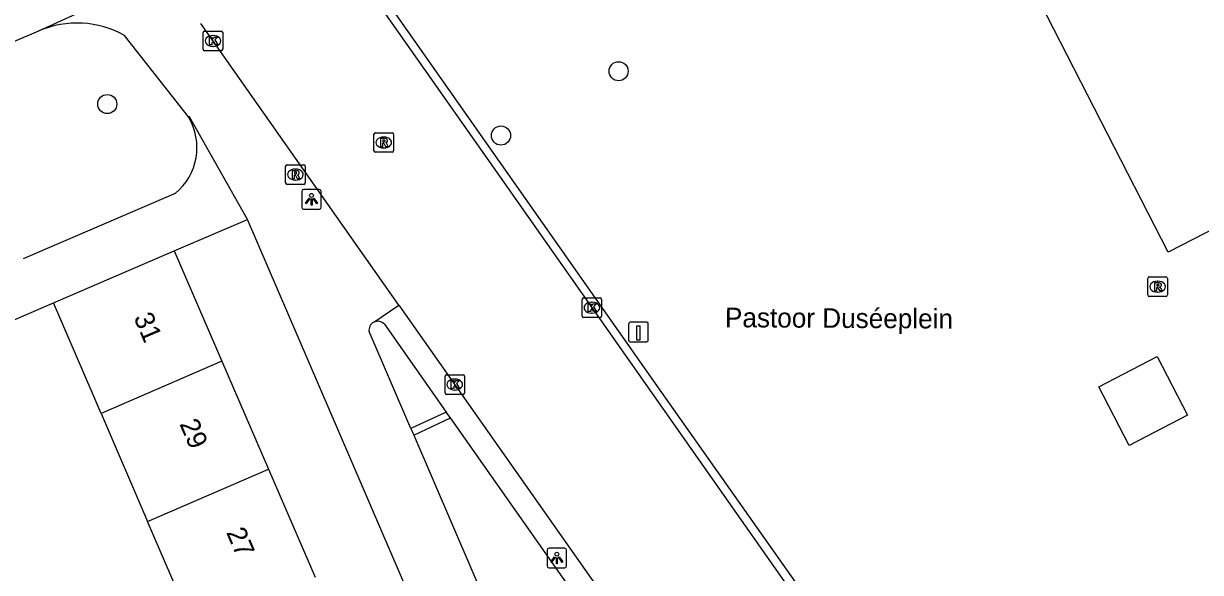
# Model space of a CAD drawing. Extents: x 159353 to 160616, y 385893 to 387321.
# Drawn here: x 159691.6 to 159751.8, y 386412.6 to 386440.7 of the extents above; entities that cross this region are included whole.
import ezdxf

# ---------------------------------------------------------------- set-up
doc = ezdxf.new("R2010")
doc.units = 0
for name, color, linetype in [('IMGEO_Boom', 7, 'Continuous'), ('IMGEO_Kolk', 7, 'Continuous'), ('IMGEO_Laadpaal', 7, 'Continuous'), ('IMGEO_Lichtpunt', 7, 'Continuous'), ('IMGEO_Muur', 7, 'Continuous'), ('IMGEO_Openbare_ruimte_label', 7, 'Continuous'), ('IMGEO_Pand', 7, 'Continuous'), ('IMGEO_Pand_nummerreeks', 7, 'Continuous'), ('IMGEO_Rijbaan_lokaal_gesloten', 7, 'Continuous'), ('IMGEO_Rijbaan_lokaal_open', 7, 'Continuous'), ('IMGEO_Rioolput', 7, 'Continuous'), ('IMGEO_Voetpad_open', 7, 'Continuous')]:
    doc.layers.add(name, color=color, linetype=linetype)

msp = doc.modelspace()

# ---------------------------------------------------------------- linework, layer by layer
at = {"layer": 'IMGEO_Boom'}
for centre in [(159722.042, 386438.211), (159695.87, 386436.533), (159716.022, 386434.92)]:
    msp.add_circle(centre, 0.489, dxfattribs=at)
at = {"layer": 'IMGEO_Kolk'}
for p, q in [((159700.777, 386439.335), (159700.777, 386440.187)), ((159700.852, 386440.261), (159701.704, 386440.261)), ((159701.265, 386440.041), (159701.29, 386440.041)), ((159701.778, 386440.187), (159701.778, 386439.335)), ((159701.288, 386439.481), (159701.263, 386439.481)), ((159701.704, 386439.261), (159700.852, 386439.261)), ((159720.171, 386425.684), (159720.171, 386426.536)), ((159720.246, 386426.61), (159721.098, 386426.61)), ((159720.659, 386426.39), (159720.684, 386426.39)), ((159721.172, 386426.536), (159721.172, 386425.684)), ((159721.098, 386425.61), (159720.246, 386425.61)), ((159720.682, 386425.83), (159720.657, 386425.83)), ((159713.157, 386421.75), (159713.157, 386422.602)), ((159713.232, 386422.676), (159714.084, 386422.676)), ((159714.158, 386422.602), (159714.158, 386421.75)), ((159713.645, 386422.456), (159713.67, 386422.456)), ((159714.084, 386421.676), (159713.232, 386421.676)), ((159713.668, 386421.896), (159713.643, 386421.896))]:
    msp.add_line(p, q, dxfattribs=at)
for points in [[(159700.777, 386439.335), (159700.777, 386440.187)], [(159700.852, 386440.261), (159701.704, 386440.261)], [(159701.778, 386440.187), (159701.778, 386439.335)], [(159701.098, 386439.961), (159701.221, 386439.961), (159701.221, 386439.81), (159701.351, 386439.961), (159701.515, 386439.961), (159701.369, 386439.81), (159701.522, 386439.561), (159701.37, 386439.561), (159701.285, 386439.725), (159701.221, 386439.658), (159701.221, 386439.561), (159701.098, 386439.561), (159701.098, 386439.961)], [(159701.704, 386439.261), (159700.852, 386439.261)], [(159720.171, 386425.684), (159720.171, 386426.536)], [(159720.246, 386426.61), (159721.098, 386426.61)], [(159720.492, 386426.31), (159720.615, 386426.31), (159720.615, 386426.159), (159720.745, 386426.31), (159720.909, 386426.31), (159720.763, 386426.159), (159720.916, 386425.91), (159720.764, 386425.91), (159720.679, 386426.074), (159720.615, 386426.007), (159720.615, 386425.91), (159720.492, 386425.91), (159720.492, 386426.31)], [(159721.172, 386426.536), (159721.172, 386425.684)], [(159721.098, 386425.61), (159720.246, 386425.61)], [(159713.157, 386421.75), (159713.157, 386422.602)], [(159713.232, 386422.676), (159714.084, 386422.676)], [(159714.158, 386422.602), (159714.158, 386421.75)], [(159713.478, 386422.376), (159713.601, 386422.376), (159713.601, 386422.225), (159713.731, 386422.376), (159713.895, 386422.376), (159713.749, 386422.225), (159713.902, 386421.976), (159713.75, 386421.976), (159713.665, 386422.14), (159713.601, 386422.073), (159713.601, 386421.976), (159713.478, 386421.976), (159713.478, 386422.376)], [(159714.084, 386421.676), (159713.232, 386421.676)]]:
    msp.add_lwpolyline(points, dxfattribs=at)
for centre, start, end in [((159700.854, 386440.185), 91.55205, 178.44795), ((159700.854, 386440.185), 91.55205, 178.44795), ((159701.702, 386440.185), 1.55205, 88.44795), ((159701.702, 386440.185), 1.55205, 88.44795), ((159700.854, 386439.337), 181.55205, 268.44795), ((159700.854, 386439.337), 181.55205, 268.44795), ((159701.702, 386439.337), 271.55205, 358.44795), ((159701.702, 386439.337), 271.55205, 358.44795), ((159720.248, 386426.534), 91.55205, 178.44795), ((159720.248, 386426.534), 91.55205, 178.44795), ((159721.096, 386426.534), 1.55205, 88.44795), ((159721.096, 386426.534), 1.55205, 88.44795), ((159720.248, 386425.686), 181.55205, 268.44795), ((159720.248, 386425.686), 181.55205, 268.44795), ((159721.096, 386425.686), 271.55205, 358.44795), ((159721.096, 386425.686), 271.55205, 358.44795), ((159713.234, 386422.6), 91.55205, 178.44795), ((159713.234, 386422.6), 91.55205, 178.44795), ((159714.082, 386422.6), 1.55205, 88.44795), ((159714.082, 386422.6), 1.55205, 88.44795), ((159713.234, 386421.752), 181.55205, 268.44795), ((159713.234, 386421.752), 181.55205, 268.44795), ((159714.082, 386421.752), 271.55205, 358.44795), ((159714.082, 386421.752), 271.55205, 358.44795)]:
    msp.add_arc(centre, 0.0765, start, end, dxfattribs=at)
for centre, major_axis, ratio, start_param, end_param in [((159701.264, 386439.761), (-0.387, 0.002), 0.722429, 4.712389, 7.853982), ((159701.289, 386439.761), (-0.39, 0.002), 0.717154, 1.570796, 4.712389), ((159720.658, 386426.11), (-0.387, 0.002), 0.722429, 4.712389, 7.853982), ((159720.683, 386426.11), (-0.39, 0.002), 0.717154, 1.570796, 4.712389), ((159713.644, 386422.176), (-0.387, 0.002), 0.722429, 4.712389, 7.853982), ((159713.669, 386422.176), (-0.39, 0.002), 0.717154, 1.570796, 4.712389)]:
    msp.add_ellipse(centre, major_axis=major_axis, ratio=ratio, start_param=start_param, end_param=end_param, dxfattribs=at)
at = {"layer": 'IMGEO_Laadpaal'}
for p, q in [((159722.557, 386425.28), (159722.557, 386424.439)), ((159722.557, 386425.28), (159722.557, 386424.439)), ((159723.473, 386425.364), (159722.632, 386425.364)), ((159723.473, 386425.364), (159722.632, 386425.364)), ((159723.557, 386424.448), (159723.557, 386425.289)), ((159723.557, 386424.448), (159723.557, 386425.289)), ((159722.641, 386424.364), (159723.482, 386424.364)), ((159722.641, 386424.364), (159723.482, 386424.364))]:
    msp.add_line(p, q, dxfattribs=at)
msp.add_lwpolyline([(159722.972, 386425.177), (159723.132, 386425.177), (159723.132, 386424.444), (159722.972, 386424.444), (159722.972, 386425.177)], dxfattribs=at)
for centre, start, end in [((159722.635, 386425.286), 92.4484, 184.28452), ((159722.635, 386425.286), 92.4484, 184.28452), ((159723.479, 386425.286), 2.4484, 94.28452), ((159723.479, 386425.286), 2.4484, 94.28452), ((159722.635, 386424.442), 182.4484, 274.28452), ((159722.635, 386424.442), 182.4484, 274.28452), ((159723.479, 386424.442), 272.4484, 4.28452), ((159723.479, 386424.442), 272.4484, 4.28452)]:
    msp.add_arc(centre, 0.0779, start, end, dxfattribs=at)
at = {"layer": 'IMGEO_Lichtpunt'}
for p, q in [((159705.826, 386432.059), (159705.826, 386431.252)), ((159705.826, 386432.059), (159705.826, 386431.252)), ((159706.728, 386432.154), (159705.92, 386432.154)), ((159706.728, 386432.154), (159705.92, 386432.154)), ((159706.822, 386431.252), (159706.822, 386432.059)), ((159706.822, 386431.252), (159706.822, 386432.059)), ((159705.92, 386431.158), (159706.728, 386431.158)), ((159705.92, 386431.158), (159706.728, 386431.158)), ((159718.381, 386413.7), (159718.381, 386412.893)), ((159718.381, 386413.7), (159718.381, 386412.893)), ((159719.283, 386413.795), (159718.475, 386413.795)), ((159719.283, 386413.795), (159718.475, 386413.795)), ((159719.377, 386412.893), (159719.377, 386413.7)), ((159719.377, 386412.893), (159719.377, 386413.7)), ((159718.475, 386412.799), (159719.283, 386412.799)), ((159718.475, 386412.799), (159719.283, 386412.799))]:
    msp.add_line(p, q, dxfattribs=at)
for points in [[(159706.2, 386431.723), (159706.239, 386431.695), (159706.051, 386431.433), (159706.013, 386431.46), (159706.2, 386431.723)], [(159706.302, 386431.675), (159706.349, 386431.675), (159706.349, 386431.353), (159706.302, 386431.353), (159706.302, 386431.675)], [(159706.412, 386431.695), (159706.45, 386431.722), (159706.637, 386431.46), (159706.598, 386431.432), (159706.412, 386431.695)], [(159718.755, 386413.364), (159718.794, 386413.336), (159718.606, 386413.074), (159718.568, 386413.101), (159718.755, 386413.364)], [(159718.857, 386413.316), (159718.904, 386413.316), (159718.904, 386412.994), (159718.857, 386412.994), (159718.857, 386413.316)], [(159718.967, 386413.336), (159719.005, 386413.363), (159719.192, 386413.101), (159719.153, 386413.073), (159718.967, 386413.336)]]:
    msp.add_lwpolyline(points, dxfattribs=at)
for centre in [(159706.325, 386431.857), (159718.88, 386413.498)]:
    msp.add_circle(centre, 0.0994, dxfattribs=at)
for centre, start, end in [((159705.92, 386432.059), 90, 180), ((159705.92, 386432.059), 90, 180), ((159706.728, 386432.059), 0, 90), ((159706.728, 386432.059), 0, 90), ((159705.92, 386431.252), 180, 270), ((159705.92, 386431.252), 180, 270), ((159706.728, 386431.252), 270, 0), ((159706.728, 386431.252), 270, 360), ((159718.475, 386413.7), 90, 180), ((159718.475, 386413.7), 90, 180), ((159719.283, 386413.7), 0, 90), ((159719.283, 386413.7), 0, 90), ((159718.475, 386412.893), 180, 270), ((159718.475, 386412.893), 180, 270), ((159719.283, 386412.893), 270, 0), ((159719.283, 386412.893), 270, 360)]:
    msp.add_arc(centre, 0.0946, start, end, dxfattribs=at)
at = {"layer": 'IMGEO_Muur'}
msp.add_lwpolyline([(159679.395, 386420.437), (159693.115, 386426.354)], dxfattribs=at)
at = {"layer": 'IMGEO_Pand'}
for points in [[(159755.254, 386431.554), (159750.18, 386428.951), (159740.866, 386447.103), (159736.596, 386444.912), (159724.093, 386469.28)], [(159693.115, 386426.354), (159699.301, 386429.028)], [(159699.301, 386429.028), (159701.741, 386423.368)], [(159695.555, 386420.693), (159695.094, 386421.763), (159693.115, 386426.354)], [(159701.741, 386423.368), (159695.555, 386420.693)], [(159701.741, 386423.368), (159704.122, 386417.845)], [(159749.604, 386423.606), (159751.159, 386420.617), (159748.172, 386419.063), (159746.617, 386422.052), (159749.604, 386423.606)], [(159695.555, 386420.693), (159697.937, 386415.169)], [(159697.937, 386415.169), (159704.122, 386417.845)], [(159704.122, 386417.845), (159706.504, 386412.322)], [(159700.318, 386409.646), (159697.937, 386415.169)]]:
    msp.add_lwpolyline(points, dxfattribs=at)
at = {"layer": 'IMGEO_Rijbaan_lokaal_gesloten'}
for points in [[(159707.835, 386444.365), (159715.94, 386432.833), (159733.644, 386407.669)], [(159710.797, 386426.243), (159700.653, 386440.652)], [(159710.797, 386426.243), (159726.156, 386404.427), (159727.573, 386402.742), (159727.984, 386402.3)]]:
    msp.add_lwpolyline(points, dxfattribs=at)
at = {"layer": 'IMGEO_Rijbaan_lokaal_open'}
msp.add_lwpolyline([(159734.449, 386407.466), (159732.63, 386409.903), (159724.262, 386421.763), (159708.201, 386444.622)], dxfattribs=at)
at = {"layer": 'IMGEO_Rioolput'}
for p, q in [((159709.521, 386434.14), (159709.521, 386434.992)), ((159709.596, 386435.066), (159710.448, 386435.066)), ((159710.009, 386434.846), (159710.034, 386434.846)), ((159710.522, 386434.992), (159710.522, 386434.14)), ((159710.448, 386434.066), (159709.596, 386434.066)), ((159710.032, 386434.286), (159710.007, 386434.286)), ((159705.074, 386433.422), (159705.926, 386433.422)), ((159704.999, 386432.496), (159704.999, 386433.348)), ((159705.487, 386433.202), (159705.512, 386433.202)), ((159706, 386433.348), (159706, 386432.496)), ((159705.926, 386432.422), (159705.074, 386432.422)), ((159705.51, 386432.642), (159705.485, 386432.642)), ((159749.131, 386426.76), (159749.131, 386427.612)), ((159749.206, 386427.686), (159750.058, 386427.686)), ((159749.619, 386427.466), (159749.644, 386427.466)), ((159750.132, 386427.612), (159750.132, 386426.76)), ((159749.642, 386426.906), (159749.617, 386426.906)), ((159750.058, 386426.686), (159749.206, 386426.686))]:
    msp.add_line(p, q, dxfattribs=at)
for points in [[(159709.521, 386434.14), (159709.521, 386434.992)], [(159709.596, 386435.066), (159710.448, 386435.066)], [(159710.11, 386434.764), (159709.858, 386434.766), (159709.858, 386434.366)], [(159710.036, 386434.685), (159709.982, 386434.685), (159709.982, 386434.604)], [(159709.982, 386434.604), (159710.034, 386434.604)], [(159710.522, 386434.992), (159710.522, 386434.14)], [(159710.448, 386434.066), (159709.596, 386434.066)], [(159709.858, 386434.366), (159709.982, 386434.366), (159709.982, 386434.528), (159709.993, 386434.528)], [(159710.04, 386434.499), (159710.111, 386434.366), (159710.251, 386434.366), (159710.186, 386434.492)], [(159705.074, 386433.422), (159705.926, 386433.422)], [(159704.999, 386432.496), (159704.999, 386433.348)], [(159705.588, 386433.12), (159705.336, 386433.122), (159705.336, 386432.722)], [(159705.336, 386432.722), (159705.46, 386432.722), (159705.46, 386432.884), (159705.471, 386432.884)], [(159705.514, 386433.041), (159705.46, 386433.041), (159705.46, 386432.96)], [(159705.46, 386432.96), (159705.512, 386432.96)], [(159705.518, 386432.855), (159705.589, 386432.722), (159705.729, 386432.722), (159705.664, 386432.848)], [(159706, 386433.348), (159706, 386432.496)], [(159705.926, 386432.422), (159705.074, 386432.422)], [(159749.131, 386426.76), (159749.131, 386427.612)], [(159749.206, 386427.686), (159750.058, 386427.686)], [(159749.72, 386427.384), (159749.468, 386427.386), (159749.468, 386426.986)], [(159750.132, 386427.612), (159750.132, 386426.76)], [(159749.468, 386426.986), (159749.592, 386426.986), (159749.592, 386427.148), (159749.603, 386427.148)], [(159749.646, 386427.305), (159749.592, 386427.305), (159749.592, 386427.224)], [(159749.592, 386427.224), (159749.644, 386427.224)], [(159749.65, 386427.119), (159749.721, 386426.986), (159749.861, 386426.986), (159749.796, 386427.112)], [(159750.058, 386426.686), (159749.206, 386426.686)]]:
    msp.add_lwpolyline(points, dxfattribs=at)
for centre, radius, start, end in [((159709.598, 386434.99), 0.0765, 91.55205, 178.44795), ((159709.598, 386434.99), 0.0765, 91.55205, 178.44795), ((159710.018, 386434.793), 0.19, 274.7715, 282.96867), ((159710.042, 386434.589), 0.0964, 77.00612, 93.18647), ((159710.056, 386434.646), 0.0378, 276.66336, 79.67722), ((159710.109, 386434.654), 0.109, 350.36119, 89.41601), ((159710.107, 386434.654), 0.112, 277.58423, 350.98172), ((159710.446, 386434.99), 0.0765, 1.55205, 88.44795), ((159710.446, 386434.99), 0.0765, 1.55205, 88.44795), ((159709.598, 386434.142), 0.0765, 181.55205, 268.44795), ((159709.598, 386434.142), 0.0765, 181.55205, 268.44795), ((159709.992, 386434.475), 0.0533, 26.02933, 88.69889), ((159710.091, 386434.439), 0.108, 29.51342, 73.79051), ((159710.446, 386434.142), 0.0765, 271.55205, 358.44795), ((159710.446, 386434.142), 0.0765, 271.55205, 358.44795), ((159705.076, 386433.346), 0.0765, 91.55205, 178.44795), ((159705.076, 386433.346), 0.0765, 91.55205, 178.44795), ((159705.924, 386433.346), 0.0765, 1.55205, 88.44795), ((159705.924, 386433.346), 0.0765, 1.55205, 88.44795), ((159705.47, 386432.831), 0.0533, 26.02933, 88.69889), ((159705.496, 386433.149), 0.19, 274.7715, 282.96867), ((159705.52, 386432.945), 0.0964, 77.00612, 93.18647), ((159705.534, 386433.002), 0.0378, 276.66336, 79.67722), ((159705.587, 386433.01), 0.109, 350.36119, 89.41601), ((159705.585, 386433.01), 0.112, 277.58423, 350.98172), ((159705.569, 386432.795), 0.108, 29.51342, 73.79051), ((159705.076, 386432.498), 0.0765, 181.55205, 268.44795), ((159705.076, 386432.498), 0.0765, 181.55205, 268.44795), ((159705.924, 386432.498), 0.0765, 271.55205, 358.44795), ((159705.924, 386432.498), 0.0765, 271.55205, 358.44795), ((159749.208, 386427.61), 0.0765, 91.55205, 178.44795), ((159749.208, 386427.61), 0.0765, 91.55205, 178.44795), ((159749.719, 386427.274), 0.109, 350.36119, 89.41601), ((159750.056, 386427.61), 0.0765, 1.55205, 88.44795), ((159750.056, 386427.61), 0.0765, 1.55205, 88.44795), ((159749.208, 386426.762), 0.0765, 181.55205, 268.44795), ((159749.208, 386426.762), 0.0765, 181.55205, 268.44795), ((159749.602, 386427.095), 0.0533, 26.02933, 88.69889), ((159749.628, 386427.413), 0.19, 274.7715, 282.96867), ((159749.652, 386427.209), 0.0964, 77.00612, 93.18647), ((159749.666, 386427.266), 0.0378, 276.66336, 79.67722), ((159749.717, 386427.274), 0.112, 277.58423, 350.98172), ((159749.701, 386427.059), 0.108, 29.51342, 73.79051), ((159750.056, 386426.762), 0.0765, 271.55205, 358.44795), ((159750.056, 386426.762), 0.0765, 271.55205, 358.44795)]:
    msp.add_arc(centre, radius, start, end, dxfattribs=at)
for centre, major_axis, ratio, start_param, end_param in [((159710.008, 386434.566), (-0.387, 0.002), 0.722429, 4.712389, 7.853982), ((159710.033, 386434.566), (-0.39, 0.002), 0.717154, 1.570796, 4.712389), ((159705.486, 386432.922), (-0.387, 0.002), 0.722429, 4.712389, 7.853982), ((159705.511, 386432.922), (-0.39, 0.002), 0.717154, 1.570796, 4.712389), ((159749.618, 386427.186), (-0.387, 0.002), 0.722429, 4.712389, 7.853982), ((159749.643, 386427.186), (-0.39, 0.002), 0.717154, 1.570796, 4.712389)]:
    msp.add_ellipse(centre, major_axis=major_axis, ratio=ratio, start_param=start_param, end_param=end_param, dxfattribs=at)
at = {"layer": 'IMGEO_Voetpad_open'}
for points in [[(159692.365, 386440.279), (159698.141, 386442.927)], [(159684.998, 386437.135), (159692.365, 386440.279)], [(159700.029, 386435.875), (159696.755, 386440.037)], [(159703.042, 386430.628), (159700.074, 386435.88), (159700.029, 386435.875)], [(159699.349, 386431.951), (159691.563, 386428.605)], [(159699.301, 386429.028), (159703.042, 386430.628)], [(159725.05, 386379.518), (159703.042, 386430.628)], [(159679.395, 386420.437), (159693.115, 386426.354)], [(159709.517, 386425.368), (159710.797, 386426.243)], [(159710.051, 386425.266), (159713.22, 386420.768)], [(159711.399, 386419.936), (159709.271, 386424.884)], [(159713.22, 386420.768), (159711.399, 386419.936)], [(159713.432, 386420.467), (159713.22, 386420.768)], [(159711.553, 386419.579), (159713.432, 386420.467)], [(159720.825, 386409.972), (159713.432, 386420.467)], [(159711.399, 386419.936), (159711.553, 386419.579)], [(159711.553, 386419.579), (159716.505, 386408.067)]]:
    msp.add_lwpolyline(points, dxfattribs=at)
for centre, radius, start, end in [((159694.315, 386435.709), 4.969, 60.58448, 113.10501), ((159697.392, 386434.311), 3.066, 309.66912, 30.66829), ((159709.715, 386424.963), 0.451, 116.07463, 190.04015), ((159709.716, 386424.961), 0.453, 42.31622, 116.05602)]:
    msp.add_arc(centre, radius, start, end, dxfattribs=at)

# ---------------------------------------------------------------- texts
at = {"layer": 'IMGEO_Openbare_ruimte_label'}
msp.add_text('Pastoor Duséeplein', height=1, rotation=359.65623, dxfattribs=at).set_placement((159727.484, 386425.112))
at = {"layer": 'IMGEO_Pand_nummerreeks'}
for s, p in [('31', (159697.203, 386425.61)), ('29', (159699.552, 386420.163)), ('27', (159701.945, 386414.612))]:
    msp.add_text(s, height=1, rotation=293.32256, dxfattribs=at).set_placement(p)

doc.saveas('drawing.dxf')
